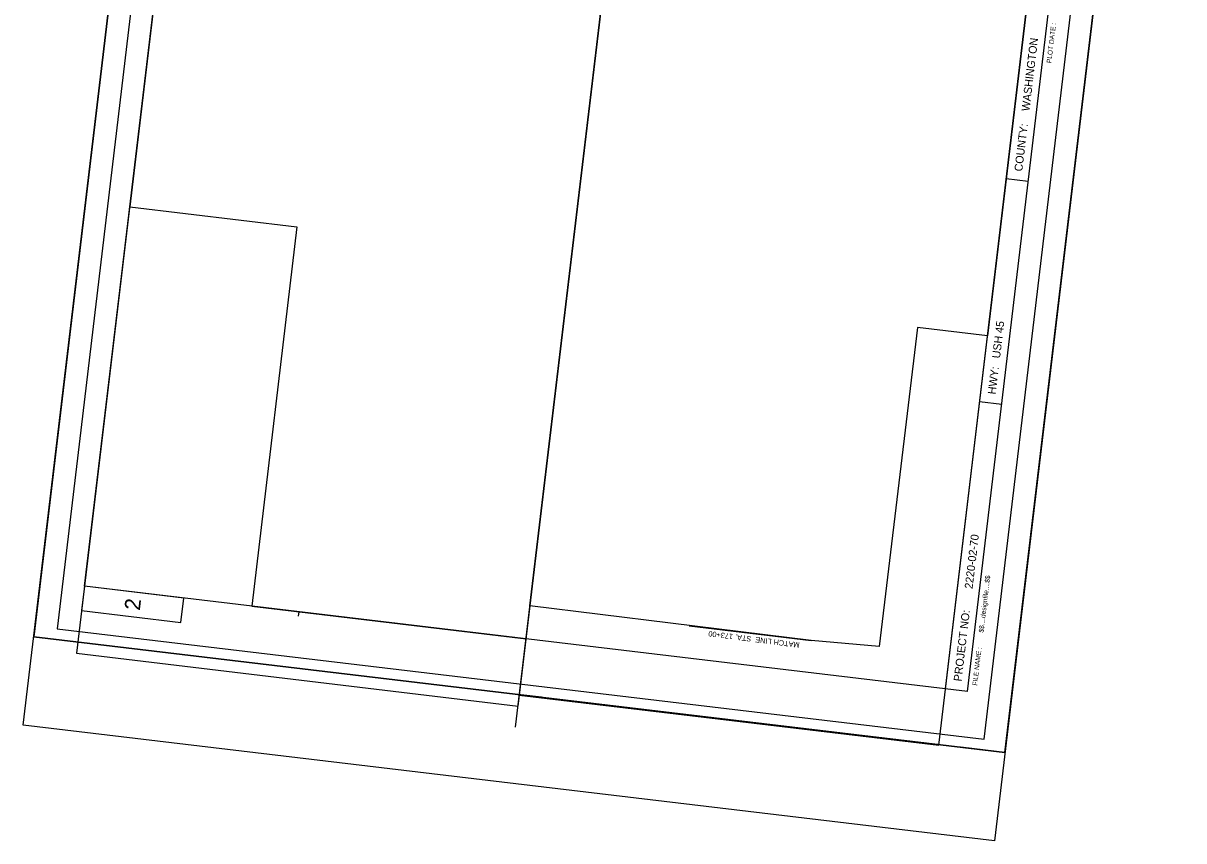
# Model space of a CAD drawing. Extents: x 361130 to 362436, y 140169 to 142087.
# Drawn here: x 361130 to 362436, y 140169 to 141089 of the extents above; entities that cross this region are included whole.
import ezdxf

# ---------------------------------------------------------------- set-up
doc = ezdxf.new("R2010")
doc.units = 0
for name, color, linetype in [('Default', 7, 'Continuous'), ('P_ALI_20', 7, 'Continuous'), ('P_ALI_200_Sta', 7, 'Continuous'), ('P_ALI_20_PIData', 7, 'Continuous'), ('P_ALI_20_Tic', 7, 'Continuous'), ('P_ALI_50_Equation', 7, 'Continuous'), ('P_ALI_50_PIData', 7, 'Continuous'), ('P_ALI_50_Tic', 7, 'Continuous')]:
    doc.layers.add(name, color=color, linetype=linetype)

msp = doc.modelspace()

# ---------------------------------------------------------------- linework, layer by layer
msp.add_lwpolyline([(361130.4, 140299.5), (361331.5, 141987.6), (362423.8, 141857.5), (362222.7, 140169.4), (361130.4, 140299.5)])
at = {"layer": 'Default'}
for points in [[(361190.4, 140380.5), (361686.9, 140321), (361864.3, 141810.6), (361367.8, 141870.1)], [(361190.4, 140380.5), (361686.9, 140321), (361864.3, 141810.6), (361367.8, 141870.1)], [(361190.4, 140380.5), (361686.9, 140321), (361864.3, 141810.6), (361367.8, 141870.1)], [(361688.3, 140333.4), (362160, 140276.9), (362337.4, 141766.3), (361865.7, 141822.8)], [(361688.3, 140333.4), (362160, 140276.9), (362337.4, 141766.3), (361865.7, 141822.8)], [(361688.3, 140333.4), (362160, 140276.9), (362337.4, 141766.3), (361865.7, 141822.8)]]:
    msp.add_lwpolyline(points, close=True, dxfattribs=at)
at = {"layer": 'P_ALI_20'}
for p, q in [((361199.4, 140455.7), (361385.7, 142019.7)), ((361695.9, 140396.6), (361882.2, 141960.5)), ((362167.5, 140340.4), (362353.8, 141904.4)), ((362192.4, 140337.5), (362378.7, 141901.4)), ((362260.7, 140910.9), (362235.8, 140913.9)), ((362230.8, 140660.2), (362206, 140663.1)), ((362192.4, 140337.5), (361199.4, 140455.7)), ((361142.3, 140398.8), (361148.2, 140448.5)), ((361440.2, 140427.1), (361439.6, 140422.1)), ((361700.3, 140433.8), (361700.3, 140433.8)), ((361191.9, 140392.9), (361142.3, 140398.8)), ((361688.4, 140333.8), (361695.9, 140396.6)), ((361713.2, 140330.8), (361663.6, 140336.7)), ((362234.5, 140268.7), (362240.5, 140318.4)), ((362234.5, 140268.7), (362184.9, 140274.7))]:
    msp.add_line(p, q, dxfattribs=at)
msp.add_lwpolyline([(361199.4, 140455.7), (361196.1, 140428.4), (361307.8, 140415.1), (361311.1, 140442.4)], close=True, dxfattribs=at)
at = {"layer": 'P_ALI_200_Sta'}
msp.add_line((361684, 140297.3), (361870.3, 141861.2), dxfattribs=at)
at = {"layer": 'P_ALI_20_PIData'}
for points in [[(361438.2, 140859.9), (361387.4, 140433.3), (361695.9, 140396.6), (361746.9, 140825.3), (361876.1, 141909.9), (361379.7, 141969.4), (361250.2, 140882.3)], [(362093.1, 140388), (362016.4, 140394.8), (361700.3, 140433.8), (361882.2, 141960.5), (362353.8, 141904.4), (362214.8, 140737.4), (362136.1, 140746.7)]]:
    msp.add_lwpolyline(points, close=True, dxfattribs=at)
at = {"layer": 'P_ALI_20_Tic'}
msp.add_lwpolyline([(361142.3, 140398.8), (361343.3, 142086.9), (362435.6, 141956.8), (362234.5, 140268.7)], close=True, dxfattribs=at)
at = {"layer": 'P_ALI_50_Equation'}
msp.add_line((361879.2, 140411.3), (362016.4, 140394.8), dxfattribs=at)
at = {"layer": 'P_ALI_50_Tic'}
for points in [[(362234.5, 140268.7), (362435.6, 141956.8), (361343.3, 142086.9), (361142.3, 140398.8)], [(362211.1, 140283.6), (362406.9, 141927), (361364.2, 142051.2), (361168.5, 140407.8)]]:
    msp.add_lwpolyline(points, close=True, dxfattribs=at)

# ---------------------------------------------------------------- texts
at = {"layer": 'P_ALI_20'}
for s, height, rotation, p in [('PLOT DATE :', 5.4, 83.2075, (362286.6, 141043.8)), (' WASHINGTON', 9, 83.2076, (362261.6, 140986.3)), ('COUNTY:', 9, 83.2076, (362253.9, 140921.8)), (' USH 45', 9, 83.2076, (362228.5, 140708.3)), ('HWY:', 9, 83.2076, (362224, 140671.1)), (' 2220-02-70', 9, 83.2076, (362197.6, 140449.1)), ('$$....designfile....$$', 5.4, 83.2075, (362210.3, 140403.3)), ('2', 17.5, 83.2076, (361261.5, 140427.9)), ('PROJECT NO:', 9, 83.2076, (362185.6, 140348.3)), ('FILE NAME :', 5.4, 83.2076, (362203.2, 140343.7))]:
    msp.add_text(s, height=height, rotation=rotation, dxfattribs=at).set_placement(p)
at = {"layer": 'P_ALI_50_PIData'}
msp.add_text('MATCH LINE  STA. 173+00', height=6, rotation=172.7522, dxfattribs=at).set_placement((362003.9, 140392.4))

doc.saveas('drawing.dxf')
